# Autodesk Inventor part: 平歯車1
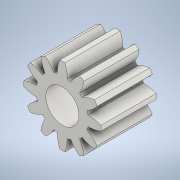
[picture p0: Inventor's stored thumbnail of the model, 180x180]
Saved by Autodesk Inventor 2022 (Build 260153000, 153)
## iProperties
Created: 2024-12
Part Number: 平歯車1
Material: Steel
Document SubType Name: Modeling
Designer: jsat7
Categories: <?xml version="1.0" encoding="UTF-16"?> <MemberInstance><Categories><FamilyTemplate><FamilyTemplateParameter ValueType="xs:double" Id="1" ObjectReferenceKey="da
Density: 1 g/cm^3
Appearance: Steel
CustomPartVersion: 1
Author: jsat7
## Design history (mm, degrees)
sketch "Sketch1"
  geometry: C1 r 3.5 at (0, 0)
  constraints: 1 centre point
  dimensions: "d0" = 7 diameter of C1 (= da_da)
extrude "Extrusion1" new body sketch "Sketch1" distance "d1" = 5 (= da_b); taper "d2" = 0 deg
workplane "Work Plane2"
sketch "Sketch2"
  geometry: C1 r 3.5 at (0, 0) reference; C2 r 3 at (0, 0)
  constraints: 1 centre point, 1 coincident
  dimensions: "d3" = 6 diameter of C2 (= da_d)
feature "ピッチ円直径" sketch "Sketch2" dims "d4" = 10, "d5" = 0
workplane "Work Plane8"
workplane "Work Plane9"
feature "平歯車" dims "da_b" = 5, "da_d" = 6, "da_aw" = 11.25, "da_da" = 7, "da_df" = 4.75, "da_dw" = 6, angle "da_beta" = 0 deg, "da_lefttooth" = 0, "da_righttooth" = 0
sketch "スケッチ3"
  geometry: C1 r 1.5 at (0, 0); 1 further point
  constraints: 1 centre point, 1 coincident
  dimensions: "d49" = 3 diameter of C1
extrude "押し出し2" cut sketch "スケッチ3" distance "d50" = 10; taper "d51" = 0 deg
body "Solid1"
body "Srf1"
other parameters: "d16" = 11.25 (= da_aw), "d17" = 0, "d34" = 15 deg (computed from da_z), "d39" = 0, "d41" = 0, "d43" = 11.25 (= da_aw), "d46" = 11.25 (= da_aw), "d47" = 0, "d48" = 0
